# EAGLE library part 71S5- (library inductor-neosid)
FILTER adjustable filter transformer with tab, type S
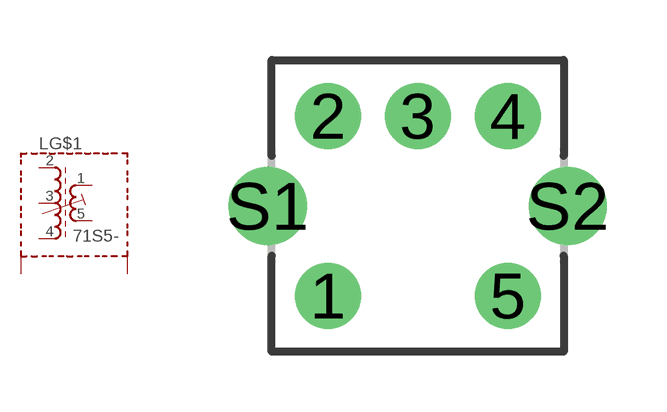
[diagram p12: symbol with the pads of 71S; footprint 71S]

Designator prefix L; gates G$1=SMF51-4 G$2=SHIELD3

## 71S5-24153 (OC_FARNELL: unknown; OC_NEWARK: unknown)  [71S]
1  G$1:A2  pas
2  G$1:A1  pas
3  G$1:Z  pas
4  G$1:E1  pas
5  G$1:E2  pas
S1  G$2:S1  pas
S2  G$2:S2  pas

## 71S5-42513 (OC_FARNELL: unknown; OC_NEWARK: unknown)  [71S]
1  G$1:E2  pas
2  G$1:E1  pas
3  G$1:Z  pas
4  G$1:A1  pas
5  G$1:A2  pas
S1  G$2:S1  pas
S2  G$2:S2  pas

## 71S5-42153 (OC_FARNELL: unknown; OC_NEWARK: unknown)  [71S]
1  G$1:A2  pas
2  G$1:E1  pas
3  G$1:Z  pas
4  G$1:A1  pas
5  G$1:E2  pas
S1  G$2:S1  pas
S2  G$2:S2  pas

## Footprint 71S (pad centres in mm)
RF COIL ASSEMBLY 2 windings, 5 pads, grid 2.25 mm
drill 1.1 round: 1 -2.25,-2.25; 2 -2.25,2.25; 3 0,2.25; 4 2.25,2.25; 5 2.25,-2.25
drill 1.3 round: S1 -3.75,0; S2 3.75,0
